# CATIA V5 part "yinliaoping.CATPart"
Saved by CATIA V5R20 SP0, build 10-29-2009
Part number: Part6
Material "Iron": density 7870 kg/m3, Young's modulus 2.11e+11 Pa, Poisson ratio 0.291, thermal expansion 1.21e-05 1/K
Bounding box of the stored display mesh (mm): x -25 to 25, y -25 to 25.5, z 0 to 110
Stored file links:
  C:\Users\86155\Desktop\Part6.CATPart
  D:\catia  20\win_b64\startup\materials\Catalog.CATMaterial
  D:\catia  20\win_b64\startup\materials\lead.jpg
  D:\catia  20\win_b64\startup\materials\black_leather.jpg
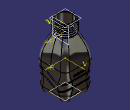
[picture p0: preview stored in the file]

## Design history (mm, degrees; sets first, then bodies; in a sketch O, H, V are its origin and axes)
Set1
  Sketch1 on xy-plane, origin (0, 0, 0), H (1, 0, 0), V (0, 1, 0)
    line L1 (25, 25) -> (25, -25)
    line L2 (25, -25) -> (-25, -25)
    line L3 (-25, -25) -> (-25, 25)
    line L4 (-25, 25) -> (25, 25)
    length L1 = 50
    length L4 = 50
    vertical: L1 V, L3 V
    horizontal: L2 H, L4 H
    equidistance: L1 L3 O, L2 L4 O
  Sketch2 on face of Pad1 from Sketch1.L1, origin (25, 0, 0), H (0, 1, 0), V (0, 0, 1)
    spline S1 through (-30, 20) (-10, 30) (10, 20) (30, 30)
  Extrude1: Element1 Sketch2, Lim1 60, Lim2 0
  MultiSel1: CommonCtxFeats ({extract ExtractElem face of Pad1 from Sketch1.L2}; {extract ExtractElem face of Fillet1}; {extract ExtractElem face of Pad1 from Sketch1.L1}; {extract ExtractElem face of Fillet1}; {extract ExtractElem face of Pad1 from Sketch1.L4}; {extract ExtractElem face of Fillet1}; {extract ExtractElem face of Pad1 from Sketch1.L3}; {extract ExtractElem face of Fillet1})
  Join1: Elements ({intersect ToIntersect1 {extract ExtractElem face of Pad1 from Sketch1.L2}, ToIntersect2 Extrude1}; {intersect ToIntersect1 {extract ExtractElem face of Fillet1}, ToIntersect2 Extrude1}; {intersect ToIntersect1 {extract ExtractElem face of Pad1 from Sketch1.L1}, ToIntersect2 Extrude1}; {intersect ToIntersect1 {extract ExtractElem face of Fillet1}, ToIntersect2 Extrude1}; {intersect ToIntersect1 {extract ExtractElem face of Pad1 from Sketch1.L4}, ToIntersect2 Extrude1}; {intersect ToIntersect1 {extract ExtractElem face of Fillet1}, ToIntersect2 Extrude1}; {intersect ToIntersect1 {extract ExtractElem face of Pad1 from Sketch1.L3}, ToIntersect2 Extrude1}; {intersect ToIntersect1 {extract ExtractElem face of Fillet1}, ToIntersect2 Extrude1})
  Plane1: type Normal, Curve Join1, RefPoint vertex [face of MultiSel1 | face of MultiSel1]
  Circle1: type CtrRad, Start 0, End 180, Center vertex [face of MultiSel1 | face of MultiSel1], Support Plane1, Radius 1, FirstDirection (0, -1, 0)
Body1 (main body), material "Iron"
  Pad1: profile Sketch1, direction (0, 0, 1), length 50
  Fillet1: on edge [face of Pad1 from Sketch1.L2 | face of Pad1 from Sketch1.L3]; edge [face of Pad1 from Sketch1.L4 | face of Pad1 from Sketch1.L1]; edge [face of Pad1 from Sketch1.L1 | face of Pad1 from Sketch1.L2]; edge [face of Pad1 from Sketch1.L3 | face of Pad1 from Sketch1.L4]
  Fillet2: radius 13, on edge [start face of Pad1 | face of Pad1 from Sketch1.L1]
  Plane2: type Offset, RefPlane end face of Pad1, Offset 40, reversed
  Sketch3 on Plane2, origin (0, 0, 90), H (1, 0, 0), V (0, -1, 0)
    circle A1 centre (0, 0) radius 15
    point P1 (15, 0)
    distance P1 V = 15
    coincidence: A1 P1
  Pad2: profile Sketch3, direction (0, 0, 1), length 20
  Sketch4 on end face of Pad1, origin (0, 0, 50), H (1, 0, 0), V (0, 1, 0)
    point P1 (25, 0)
    distance P1 V = 25
    coincidence: P1 H
  Sketch5 on start face of Pad2, origin (0, 0, 90), H (1, 0, 0), V (0, -1, 0)
    point P1 (15, 0)
    distance P1 V = 15
    coincidence: P1 H
  Loft1: solid, Sections (edge [face of Pad2 from Sketch3.A1 | start face of Pad2]; {boundary Boundary {extract ExtractElem end face of Pad1}}), EndFace end face of Pad1
  Slot1: profile Circle1, centre curve Join1
  Extrude2: Element1 Sketch2, Lim1 60, Lim2 0
  Sketch6 on face of Pad1 from Sketch1.L3, origin (-25, 0, 0), H (0, -1, 0), V (0, 0, 1)
    spline S1 through (-30, 40) (-10, 30) (10, 40) (30, 30)
  Extrude3: Element1 Sketch6, Lim1 60, Lim2 0
  MultiSel2: CommonCtxFeats ({extract ExtractElem face of Pad1 from Sketch1.L3}; {extract ExtractElem face of Fillet1}; {extract ExtractElem face of Pad1 from Sketch1.L2}; {extract ExtractElem face of Fillet1}; {extract ExtractElem face of Pad1 from Sketch1.L1}; {extract ExtractElem face of Fillet1}; {extract ExtractElem face of Pad1 from Sketch1.L4}; {extract ExtractElem face of Fillet1})
  Join2: Elements ({intersect ToIntersect1 {extract ExtractElem face of Pad1 from Sketch1.L3}, ToIntersect2 Extrude3}; {intersect ToIntersect1 {extract ExtractElem face of Fillet1}, ToIntersect2 Extrude3}; {intersect ToIntersect1 {extract ExtractElem face of Pad1 from Sketch1.L2}, ToIntersect2 Extrude3}; {intersect ToIntersect1 {extract ExtractElem face of Fillet1}, ToIntersect2 Extrude3}; {intersect ToIntersect1 {extract ExtractElem face of Pad1 from Sketch1.L1}, ToIntersect2 Extrude3}; {intersect ToIntersect1 {extract ExtractElem face of Fillet1}, ToIntersect2 Extrude3}; {intersect ToIntersect1 {extract ExtractElem face of Pad1 from Sketch1.L4}, ToIntersect2 Extrude3}; {intersect ToIntersect1 {extract ExtractElem face of Fillet1}, ToIntersect2 Extrude3})
  Plane3: type Normal, Curve Join2, RefPoint vertex [face of MultiSel2 | face of MultiSel2]
  Circle2: type CtrRad, Start 0, End 180, Center vertex [face of MultiSel2 | face of MultiSel2], Support Plane3, Radius 1, FirstDirection (1, 0, 0)
  Slot2: profile Circle2, centre curve Join2
  Shell1: IntOffset 2, Face end face of Pad2, ExtOffset 0
  Plane4: type Offset, RefPlane Plane2, Offset -2
  Point1: type OnPlane, Support Plane4, H 15, V 2.935, Direction (1, 0, 0)
  Helix1: Direction Z axis, RefPoint Point1, Pitch 3, Height 16, TaperAngle 0
  Point2: type OnCurve, Support Helix1, Length 8.699
  Point3: type OnCurve, Support Helix1, RefPoint vertex of Helix1, Length -7.588
Body2
  Sketch7 on face of Pad1 from Sketch1.L4, origin (0, 25, 0), H (-1, 0, 0), V (0, 0, 1)
    polyline C1
    polyline C2
    polyline C3
    polyline C4
    polyline C5
    polyline C6
    polyline C7
    polyline C8
    polyline C9
    polyline C10
    polyline C11
  Pad3: profile Sketch7, direction (0, 1, 0), length 0.5
  Line1: type PtDir, RefPoint vertex of Helix1, Direction (0, 1, 0), Start 0, End 10
  Line2: type PtDir, RefPoint Point1, Direction (1, 0, 0), Start 0, End 10
  Connect1: Curve1 Line1, Point1 vertex of Line1, Tension1 1, Curve2 Helix1, Point2 Point3, Tension2 1
  Connect2: Curve1 Line2, Point1 vertex of Line2, Tension1 1, Curve2 Helix1, Point2 Point2, Tension2 1
  Plane5: type Normal, Curve Connect2, RefPoint vertex of Connect2
  Circle3: type CtrRad, Start 0, End 180, Center vertex of Connect2, Support Plane5, Radius 1, FirstDirection (0, 1, 0)
  Rib1: profile Circle3, centre curve Connect2
  Body3
    Plane6: type Offset, RefPlane xy-plane, Offset 110
    Sketch8 on Plane6, origin (0, 0, 110), H (1, 0, 0), V (0, 1, 0)
      circle A1 centre (0, 0) radius 15
    Pad4: profile Sketch8, direction (0, 0, -1), length 50
  Remove1: tool Body3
